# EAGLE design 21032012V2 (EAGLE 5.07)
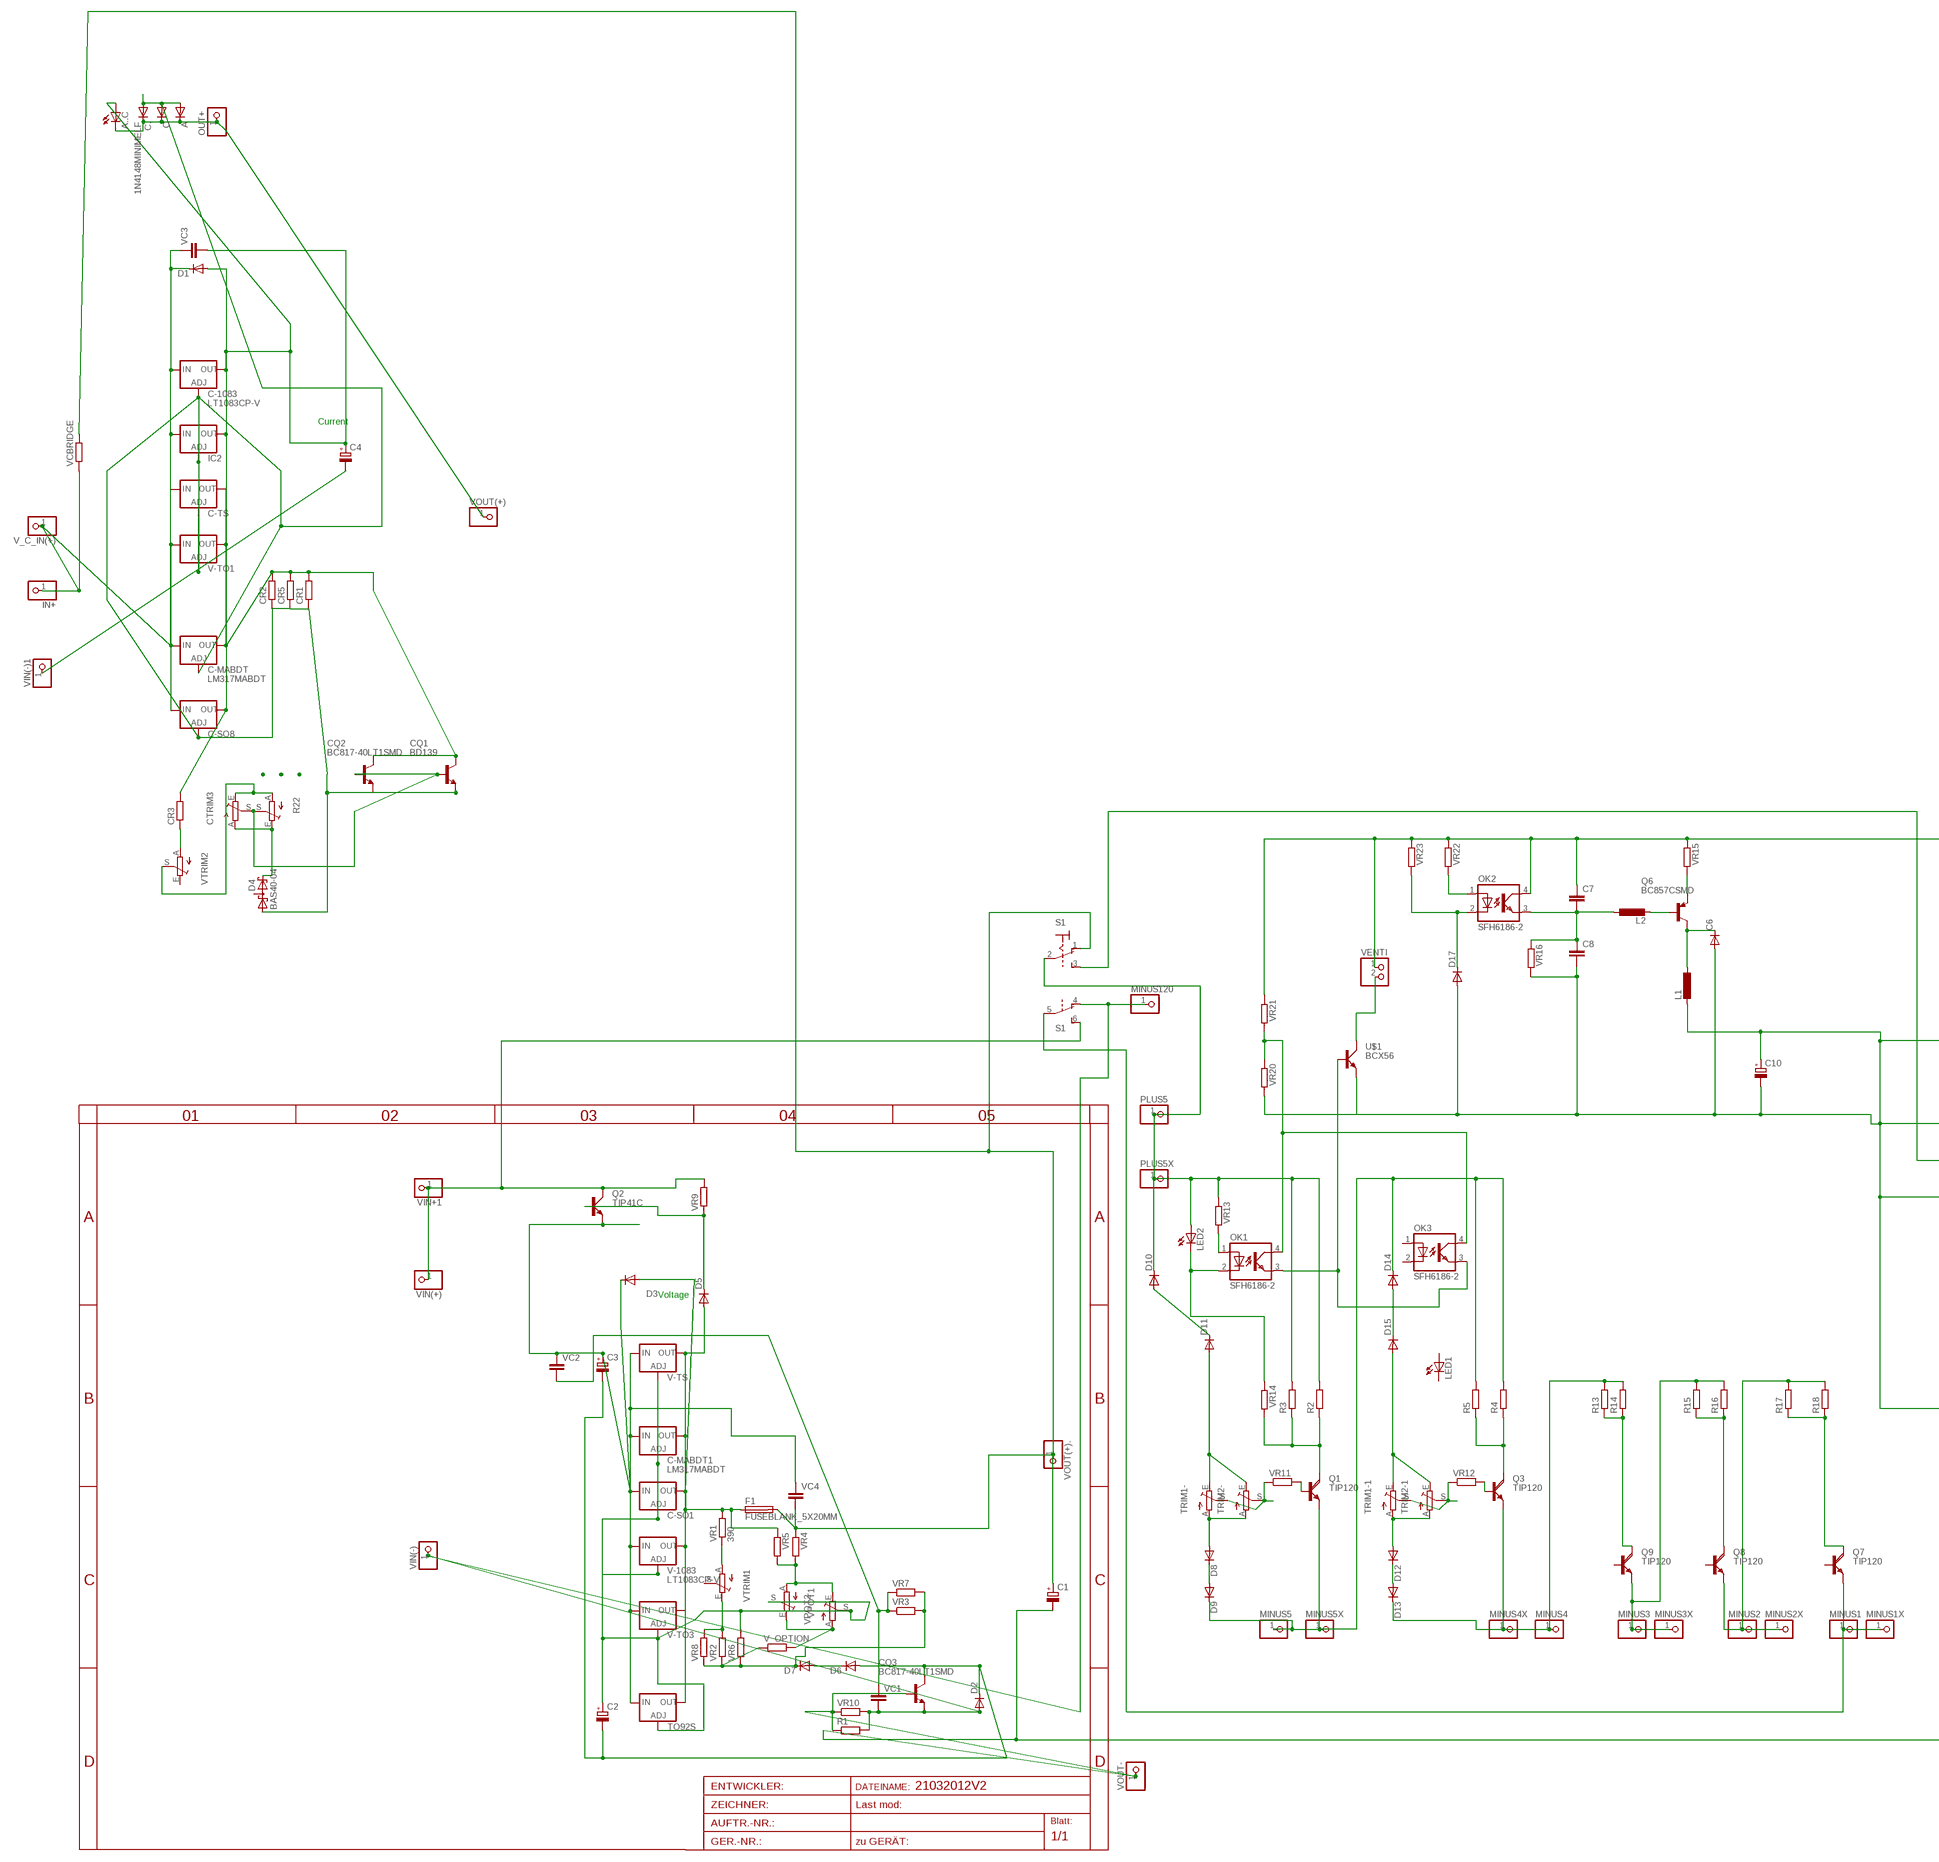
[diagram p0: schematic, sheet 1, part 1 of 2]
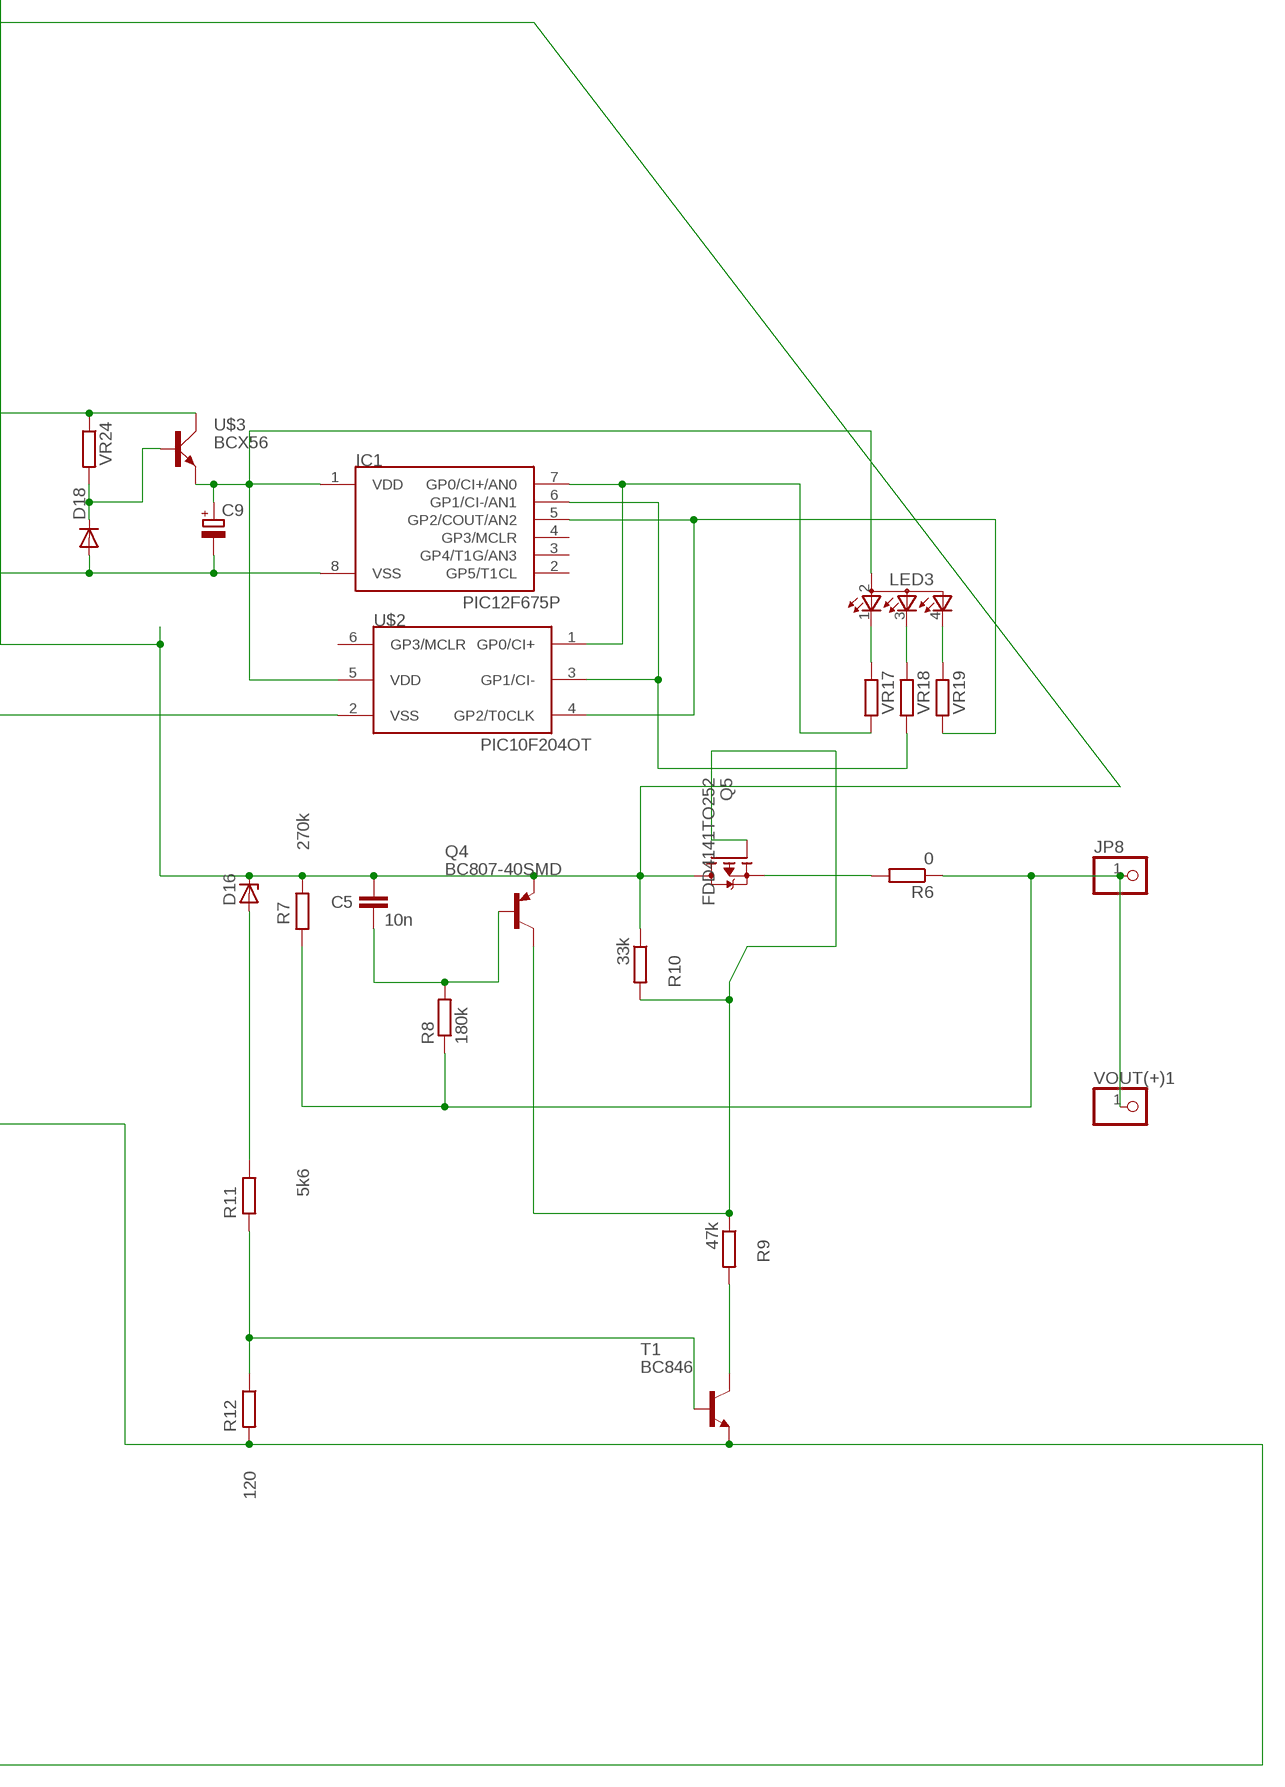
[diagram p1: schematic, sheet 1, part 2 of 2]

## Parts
A  DIODE-TO220V  [TO220ACS]
A..C  LED3MM  [LED3MM]
C  DIODE-SMB  [SMB]
C1  CPOL-EUE5-8.5  [E5-8,5]
C2  CPOL-EUE2.5-6  [E2,5-6]
C3  CPOL-EUE2.5-6  [E2,5-6]
C4  CPOL-EUE5-6  [E5-6]
C5  10n  C-EUC1206  [C1206]
C6  DIODE-SMB  [SMB]
C7  C-EUC0805  [C0805]
C8  C-EUC0805  [C0805]
C9  CPOL-EUE2.5-6  [E2,5-6]
C10  CPOL-EUE2.5-6  [E2,5-6]
C-1083  LT1083CP-V  [TO247S]
C-MABDT  LM317MABDT  [DPACK]
C-MABDT1  LM317MABDT  [DPACK]
C-SO1  LM317LM-OUTPIN7  [SO08]
C-SO8  LM317LM-OUTPIN7  [SO08]
C-TS  LM317TS  [317TS]
C.  1N4148MINIMELF  [MINIMELF]
CQ1  BD139  [TO126]
CQ2  BC817-40LT1SMD  [SOT23-BEC]
CQ3  BC817-40LT1SMD  [SOT23-BEC]
CR1  R-EU_R5025  [R5025]
CR2  R-EU_R1206  [R1206]
CR3  R-EU_0204/5  [0204/5]
CR5  R-EU_R1210  [R1210]
CTRIM3  TRIM_EU-EVND_H  [EVND8AA]
D1  DIODE-MINIMELF  [MINIMELF]
D2  DIODE-MINIMELF  [MINIMELF]
D3  DIODE-MINIMELF  [MINIMELF]
D4  BAS40-04  [SOT23]
D5  DIODE-MINIMELF  [MINIMELF]
D6  DIODE-MINIMELF  [MINIMELF]
D7  DIODE-MINIMELF  [MINIMELF]
D8  DIODE-MINIMELF  [MINIMELF]
D9  DIODE-MINIMELF  [MINIMELF]
D10  DIODE-MINIMELF  [MINIMELF]
D11  DIODE-MINIMELF  [MINIMELF]
D12  DIODE-MINIMELF  [MINIMELF]
D13  DIODE-MINIMELF  [MINIMELF]
D14  DIODE-MINIMELF  [MINIMELF]
D15  DIODE-MINIMELF  [MINIMELF]
D16  ZENER-DIODESOD80C  [SOD80C]
D17  DIODE-MINIMELF  [MINIMELF]
D18  DIODE-MINIMELF  [MINIMELF]
F1  FUSEBLANK_5X20MM  [FUSE_HOLDER_5X20MM]
IC1  PIC12F675P  [DIL8]
IC2  LM317LZS  [TO92S]
IN+  PINHD-1X1  [1X01]
JP8  PINHD-1X14.5MM  [1X4MM5]
L1  L-EUL5650M  [L5650M]
L2  L-EUL5650M  [L5650M]
LED1  LEDCHIPLED_1206  [CHIPLED_1206]
LED2  LEDCHIPLED_1206  [CHIPLED_1206]
LED3  TOPLED-3  [P-LCC-4-3]
MINUS1  PINHD-1X14.5MM  [1X4MM5]
MINUS1X  PINHD-1X11X0.4  [1X01]
MINUS2  PINHD-1X14.5MM  [1X4MM5]
MINUS2X  PINHD-1X11X0.4  [1X01]
MINUS3  PINHD-1X14.5MM  [1X4MM5]
MINUS3X  PINHD-1X11X0.4  [1X01]
MINUS4  PINHD-1X14.5MM  [1X4MM5]
MINUS4X  PINHD-1X11X0.4  [1X01]
MINUS5  PINHD-1X14.5MM  [1X4MM5]
MINUS5X  PINHD-1X11X0.4  [1X01]
MINUS120  PINHD-1X14.5MM  [1X4MM5]
OK1  SFH6186-2  [SMD4]
OK2  SFH6186-2  [SMD4]
OK3  SFH6186-2  [SMD4]
OUT+  PINHD-1X1  [1X01]
PLUS5  PINHD-1X14.5MM  [1X4MM5]
PLUS5X  PINHD-1X11X0.4  [1X01]
Q1  TIP120  [D-PAK_TO252AA]
Q2  TIP41C  [TO220AV]
Q3  TIP120  [D-PAK_TO252AA]
Q4  BC807-40SMD  [SOT23-BEC]
Q5  FDD4141TO252  [TO252]
Q6  BC857CSMD  [SOT23-BEC]
Q7  TIP120  [D-PAK_TO252AA]
Q8  TIP120  [D-PAK_TO252AA]
Q9  TIP120  [D-PAK_TO252AA]
R1  R-EU_0204/2V  [0204V]
R2  R-EU_CERAM55  [CERAM55]
R3  R-EU_CERAM55  [CERAM55]
R4  R-EU_CERAM55  [CERAM55]
R5  R-EU_CERAM55  [CERAM55]
R6  0  R-EU_R2010  [R2010]
R7  270k  R-EU_R1206  [R1206]
R8  180k  R-EU_R1206  [R1206]
R9  47k  R-EU_R1206  [R1206]
R10  33k  R-EU_R1206  [R1206]
R11  5k6  R-EU_R1206  [R1206]
R12  120  R-EU_R1206  [R1206]
R13  R-EU_CERAM55  [CERAM55]
R14  R-EU_CERAM55  [CERAM55]
R15  R-EU_CERAM55  [CERAM55]
R16  R-EU_CERAM55  [CERAM55]
R17  R-EU_CERAM55  [CERAM55]
R18  R-EU_CERAM55  [CERAM55]
R22  TRIM_EU-RAND160  [RANDL]
S1  320-938  [320-938]
T1  BC846  [SOT23]
TO92S  LM317LZS  [TO92S]
TRIM1-  TRIM_EU-EVND_H  [EVND8AA]
TRIM1-1  TRIM_EU-EVND_H  [EVND8AA]
TRIM2-  TRIM_EU-S64W  [S64W]
TRIM2-1  TRIM_EU-S64W  [S64W]
U$1  BCX56  [SOT223]
U$2  PIC10F204OT  [SOT23-6]
U$3  BCX56  [SOT223]
V-1083  LT1083CP-V  [TO247S]
V-TO1  LM317-TO3  [TO3-K02]
V-TO3  LM317-TO3  [TO3-K02]
V-TS  LM317TS  [317TS]
V_C_IN(+)  PINHD-1X11X0.4  [1X01]
V_OPTION  R-EU_0204/2V  [0204V]
VC1  C-EU050-025X075  [C050-025X075]
VC2  C-EU050-025X075  [C050-025X075]
VC3  C-EU050-025X075  [C050-025X075]
VC4  C-EUC1206  [C1206]
VCBRIDGE  R-EU_R0402  [R0402]
VENTI  PINHD-1X2  [1X02]
VIN(+)  PINHD-1X11X0.4  [1X01]
VIN(-)  PINHD-1X1  [1X01]
VIN(-)1  PINHD-1X1  [1X01]
VIN+1  PINHD-1X1  [1X01]
VOUT(+)  PINHD-1X11X0.4  [1X01]
VOUT(+)1  PINHD-1X11X0.4  [1X01]
VOUT(+).  PINHD-1X11X0.4  [1X01]
VOUT-  PINHD-1X11X0.4  [1X01]
VPOT1  TRIM_EU-RAND160  [RANDL]
VPOT2  TRIM_EU-S64W  [S64W]
VR1  390  R-EU_0207/15  [0207/15]
VR2  R-EU_0204/2V  [0204V]
VR3  R-EU_0204/5  [0204/5]
VR4  R-EU_R1206  [R1206]
VR5  R-EU_R1206  [R1206]
VR6  R-EU_R1206  [R1206]
VR7  R-EU_R1206  [R1206]
VR8  R-EU_R1206  [R1206]
VR9  R-EU_R1206  [R1206]
VR10  R-EU_0617/17  [0617/17]
VR11  R-EU_R1206  [R1206]
VR12  R-EU_R1206  [R1206]
VR13  R-EU_R1206  [R1206]
VR14  R-EU_R1206  [R1206]
VR15  R-EU_R1206  [R1206]
VR16  R-EU_R1206  [R1206]
VR17  R-EU_R1206  [R1206]
VR18  R-EU_R1206  [R1206]
VR19  R-EU_R1206  [R1206]
VR20  R-EU_R1206  [R1206]
VR21  R-EU_R1206  [R1206]
VR22  R-EU_R1206  [R1206]
VR23  R-EU_R1206  [R1206]
VR24  R-EU_R1206  [R1206]
VTRIM1  TRIM_EU-EVND_H  [EVND8AA]
VTRIM2  TRIM_EU-EVND_H  [EVND8AA]

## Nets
ADJ2: C2.+ C-MABDT1.1(ADJ) C-SO1.4(ADJ) TO92S.1(ADJ) V-1083.1(ADJ) V-TO3.2(ADJ) V-TS.1(ADJ) VPOT1.S VPOT2.S VR6.2
ADJUST: A.A C-1083.1(ADJ) C-MABDT.1(ADJ) C-SO8.4(ADJ) C-TS.1(ADJ) C..A C.A CQ1.1(E) CQ2.E CR1.1 CR2.1 CR5.1 D4.1(A1) IC2.1(ADJ) V-TO1.2(ADJ)
B: TRIM1-.S TRIM2-.S VR11.1
B1: CQ1.3(B) CQ2.B CTRIM3.S R22.S
B2: TRIM1-1.S TRIM2-1.S VR12.1
B-Q1: C5.2 Q4.B R8.2
BATT-: MINUS1.1 MINUS1X.1 Q7.3(E) S1.5(B:P)
D: Q5.3(S) R6.2
GATE: Q4.C Q5.1(G) R9.1 R10.2
IN+1: C3.+ C-MABDT1.3(IN) C-SO1.1(IN) D3.C Q2.E TO92S.3(IN) V-1083.3(IN) V-TO3.1(IN) V-TS.3(IN) VC2.1 VC4.1
IN-: CQ3.E D2.A MINUS120.1 R1.2 S1.4(B:O) VC1.2 VIN(-).1 VR10.2
INPUT+: C-1083.3(IN) C-MABDT.3(IN) C-SO8.1(IN) C-TS.3(IN) D1.C IC2.3(IN) IN+.1 V-TO1.1(IN) V_C_IN(+).1 VC3.1 VCBRIDGE.1
MINUS: CTRIM3.A D4.2(C2) R22.E
N$1: V_OPTION.2 VPOT1.E VPOT2.A
N$2: VPOT1.A VPOT2.E VR4.2 VR5.2
N$3: VR2.2 VR8.2 VTRIM1.E
N$4: VR1.1 VTRIM1.A
N$5: CTRIM3.E R22.A VTRIM2.S
N$6: CR3.1 VTRIM2.A
N$7: VC1.1 VC2.2 VR3.1 VR7.1
N$8: D13.C MINUS4.1 MINUS4X.1 Q3.3(E) R13.2 R14.2
N$9: C4.- VIN(-)1.1
N$10: D5.C Q2.B VR9.1
N$11: LED2.C OK1.2(C) VR14.1
N$12: D7.C V_OPTION.1 VR2.1 VR3.2 VR6.1 VR7.2 VR8.1
N$13: D6.C D7.A
N$14: D11.A TRIM1-.E TRIM2-.E
N$15: D8.A TRIM1-.A TRIM2-.A
N$16: D10.C LED2.A PLUS5.1 PLUS5X.1 R2.2 R3.2 S1.2(1:P) VR13.1
N$17: D10.A D11.C
N$18: R9.2 T1.3(C)
N$19: D16.A R11.1
N$20: Q1.4(C) R2.1 R3.1 VR14.2
N$21: R11.2 R12.1 T1.1(B)
N$23: OK1.1(A) VR13.2
N$24: D8.C D9.A
N$25: Q1.1(B) VR11.2
N$26: D15.A TRIM1-1.E TRIM2-1.E
N$27: D12.A TRIM1-1.A TRIM2-1.A
N$28: D9.C D14.C MINUS5.1 MINUS5X.1 Q1.3(E) R4.2 R5.2
N$29: D14.A D15.C
N$30: Q3.4(C) R4.1 R5.1
N$32: D12.C D13.A
N$33: Q3.1(B) VR12.2
N$34: C9.+ IC1.1(VDD) LED3.2(A2) U$2.5(VDD) U$3.1(E)
N$35: IC1.7(GP0/CI+/AN0) U$2.1(GP0/CI+) VR17.2
N$36: IC1.6(GP1/CI-/AN1) U$2.3(GP1/CI-) VR18.2
N$37: IC1.5(GP2/COUT/AN2) U$2.4(GP2/T0CLK) VR19.2
N$38: Q6.E VR15.2
N$39: L2.2 Q6.B
N$40: C6.C L1.1 Q6.C
N$41: D17.C OK2.2(C) VR23.2
N$42: OK2.1(A) VR22.2
N$43: C7.2 C8.1 L2.1 OK2.3(EMIT) VR16.1
N$44: OK1.4(COL) OK3.4(COL) VR20.1 VR21.2
N$45: OK1.3(EMIT) OK3.3(EMIT) U$1.3(B)
N$46: D18.C U$3.3(B) VR24.2
N$47: LED3.1(CRED) VR17.1
N$48: LED3.3(CBLUE) VR18.1
N$49: LED3.4(CGREEN) VR19.1
N$53: U$1.2(C) VENTI.2
N$56: Q9.4(C) R13.1 R14.1
N$58: Q8.4(C) R15.1 R16.1
N$59: MINUS3.1 MINUS3X.1 Q9.3(E) R15.2 R16.2
N$60: MINUS2.1 MINUS2X.1 Q8.3(E) R17.2 R18.2
N$61: Q7.4(C) R17.1 R18.1
OUT1: A..C.A C4.+ C-1083.2(OUT) C-MABDT.4(OUT) C-SO8.7(OUT) C-TS.2(OUT) CQ1.2(C) CQ2.C CR1.2 CR2.2 CR3.2 CR5.2 D1.A IC2.2(OUT) V-TO1.3(OUT) VC3.2
OUT2: C-MABDT1.4(OUT) C-SO1.7(OUT) D3.A D5.A F1.1 TO92S.2(OUT) V-1083.2(OUT) V-TO3.3(OUT) V-TS.2(OUT) VR1.2 VR5.1
OUT+: A..C.K(C) A.C C..C C.C OUT+.1 VOUT(+).1
V+OUT: JP8.1 R6.1 R7.2 R8.1 VOUT(+)1.1
V-: C1.- C6.A C8.2 C9.- C10.+ C10.- CQ3.B D17.A D18.A IC1.8(VSS) L1.2 R1.1 R12.2 T1.2(E) U$1.1(E) U$2.2(VSS) U$3.2(C) VOUT-.1 VR10.1 VR16.2 VR20.2 VR24.1
VIN+: Q2.C S1.6(B:S) VIN(+).1 VIN+1.1 VR9.2
VIRT-: C2.- C3.- CQ3.C D2.C D6.A
VOUT+: C1.+ F1.2 S1.1(1:O) VC4.2 VCBRIDGE.2 VOUT(+)..1 VR4.1
VOUT+120: C5.1 C7.1 D16.C OK2.4(COL) Q4.E Q5.2(D) R7.1 R10.1 S1.3(1:S) VENTI.1 VR15.1 VR21.1 VR22.1 VR23.1
Unconnected: D4.3(C1A2) IC1.2(GP5/T1CL) IC1.3(GP4/T1G/AN3) IC1.4(GP3/MCLR) LED1.A LED1.C OK3.1(A) OK3.2(C) Q7.1(B) Q8.1(B) Q9.1(B) U$2.6(GP3/MCLR) VTRIM1.S VTRIM2.E

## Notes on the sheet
- Current
- Voltage

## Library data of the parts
A C C6 D1-D3 D5-D15 D17 D18 = diode:DIODE-: DIODE
A..C LED1 LED2 = led:LED: LED
C1-C4 C9 C10 = rcl:CPOL-EU: POLARIZED CAPACITOR, European symbol
C5 = rcl-2:C-EU: CAPACITOR, European symbol
C7 C8 VC1-VC4 = rcl:C-EU: CAPACITOR, European symbol
C-1083 V-1083 = linear-technology-2:LT1083*: 7.5A Low Dropout Positive Adjustable Regulators
C-MABDT C-MABDT1 = v-reg:LM317?*: 500 mA Adjustable Output Positive Voltage Regulator Source: http://www.onsemi.co.jp .. LM317M-D.PDF
C-SO1 C-SO8 IC2 TO92S = v-reg-3:LM317L: Adjustable Voltage Regulator, 1.2V to 37V, 100mA
C-TS V-TS = v-reg:LM317TS: VOLTAGE REGULATOR
C. = diode-1:1N4148: DIODE
CQ1 = transistor-npn:BD139*: NPN Transistor
CQ2 CQ3 = transistor-npn:BC817*: NPN Transistor
CR1-CR3 CR5 R6-R12 V_OPTION VCBRIDGE VR1-VR24 = rcl-2:R-EU_: RESISTOR, European symbol
CTRIM3 R22 TRIM1- TRIM1-1 TRIM2- TRIM2-1 VPOT1 VPOT2 VTRIM1 VTRIM2 = pot:TRIM_EU-: POTENTIOMETER
D4 = diode:BAS40-04: Silicon Schottky Diodes General-purpose diode for high-speed switching
D16 = diode-1:ZENER-DIODE: Z-Diode
F1 = fuse:FUSE: Fuse
IC1 = microchip-5:PIC12F6*: uPC nW 1k Program Flash memory 2x Timer Comparator 10b A/D converter/ 4xIN
IN+ OUT+ VIN(-) VIN(-)1 VIN+1 = pinhead(2):PINHD-1X1: PIN HEADER
JP8 MINUS1 MINUS1X MINUS2 MINUS2X MINUS3 MINUS3X MINUS4 MINUS4X MINUS5 MINUS5X MINUS120 PLUS5 PLUS5X V_C_IN(+) VIN(+) VOUT(+) VOUT(+)1 VOUT(+). VOUT- = pinhead:PINHD-1X1: PIN HEADER
L1 L2 = rcl:L-EU: INDUCTOR, European symbol
LED3 = led:TOPLED-3: OSRAM - Hyper Multi TOPLED® (RGB) LB E673, LV E673, LT E673 - Power TOPLED® Enhanced optical Power LED (HOP2000) LS E67B, LA E67B, LO E67B, LY E67B - Hyper Multi TOPLED® Enhanced optical Power LED (HOP2000 / ATON®) LATB T66B - Hyper Multi TOPLED® Hyper-Bright LED LATB T686 Source: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
OK1-OK3 = optocoupler:SFH618?*: Optocoupler, Phototransistor Output, Low Input Current Source: http://www.vishay.com/docs/83673/sfh618.pdf
Q1 Q3 Q7-Q9 = transistor-power:TIP120: NPN DARLINGTON TRANSISTOR
Q2 = transistor-power:TIP41C: NPN TRANSISTOR
Q4 = transistor-pnp:BC807*: PNP Transistror
Q5 = transistor-fet:FDD4141: P-Channel PowerTrench® MOSFET Source: FDD4141.pdf
Q6 = transistor-pnp:BC857*: PNP Transistror
R1-R5 R13-R18 = rcl:R-EU_: RESISTOR, European symbol
S1 = switch:320-938: TOGGLE SWITCH distributor RS Components
T1 = transistor:BC846: NPN TRANSISTOR
U$1 U$3 = transistor-power:BCX56
U$2 = microchip-5:PIC10F2*: uPC nW 0,25/0,5k Program Flash memory Comparator
V-TO1 V-TO3 = v-reg:LM317-TO3: VOLTAGE REGULATOR
VENTI = pinhead(2):PINHD-1X2: PIN HEADER

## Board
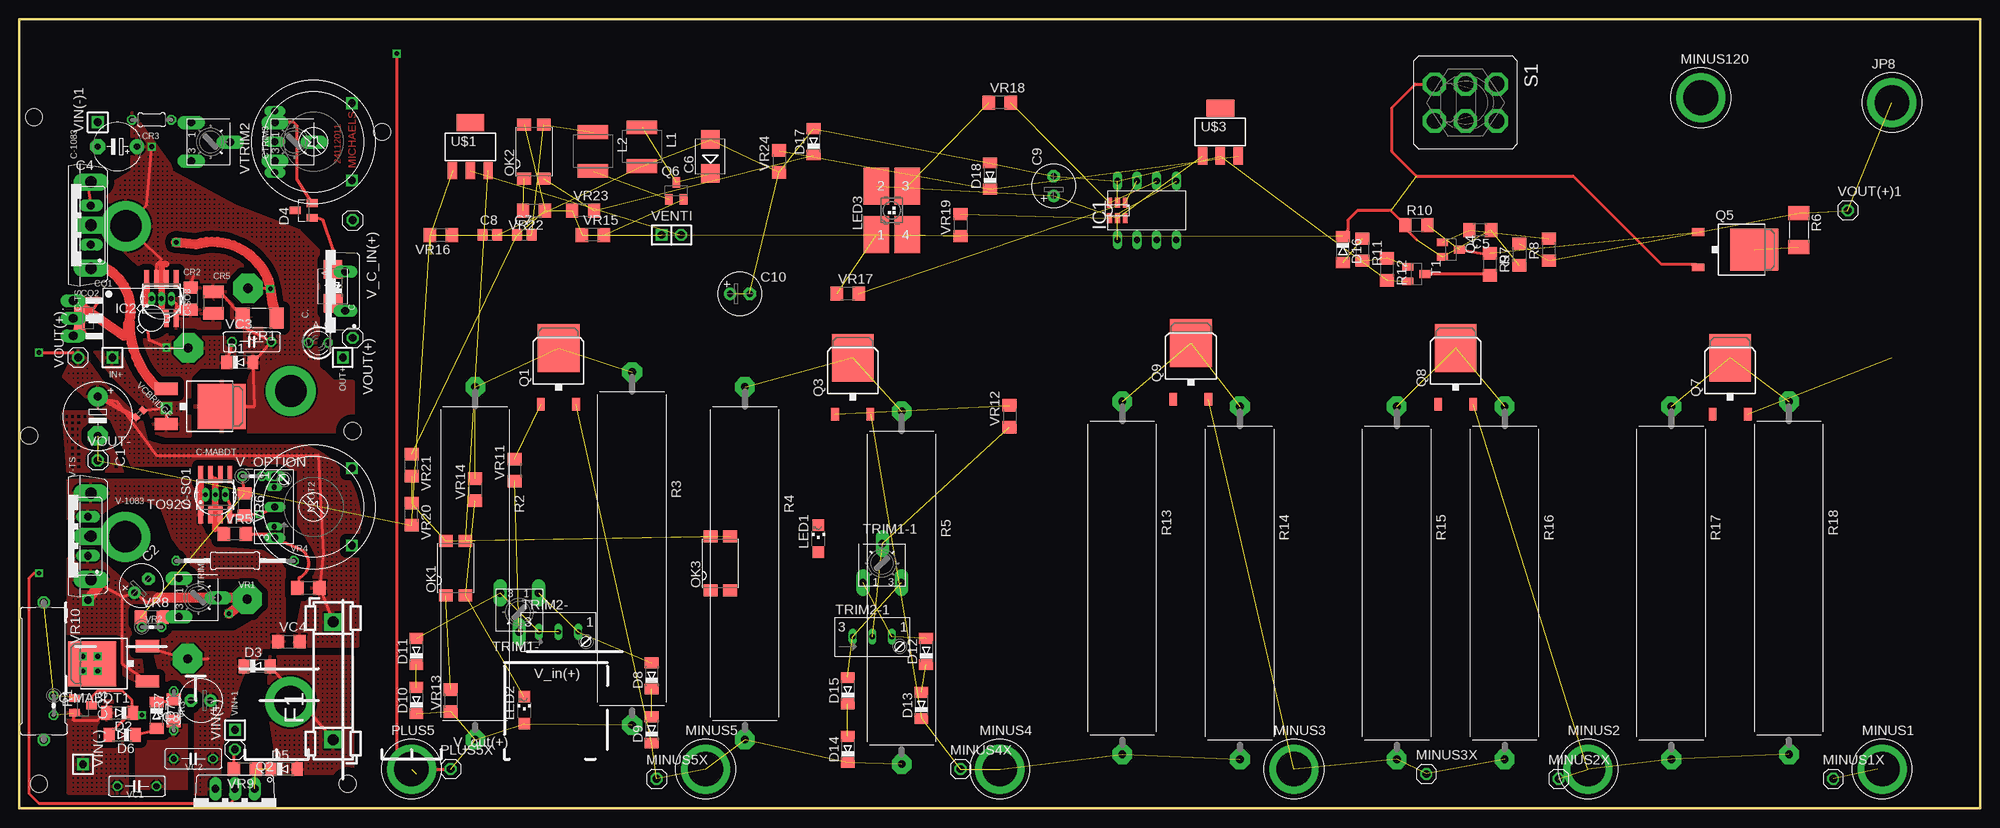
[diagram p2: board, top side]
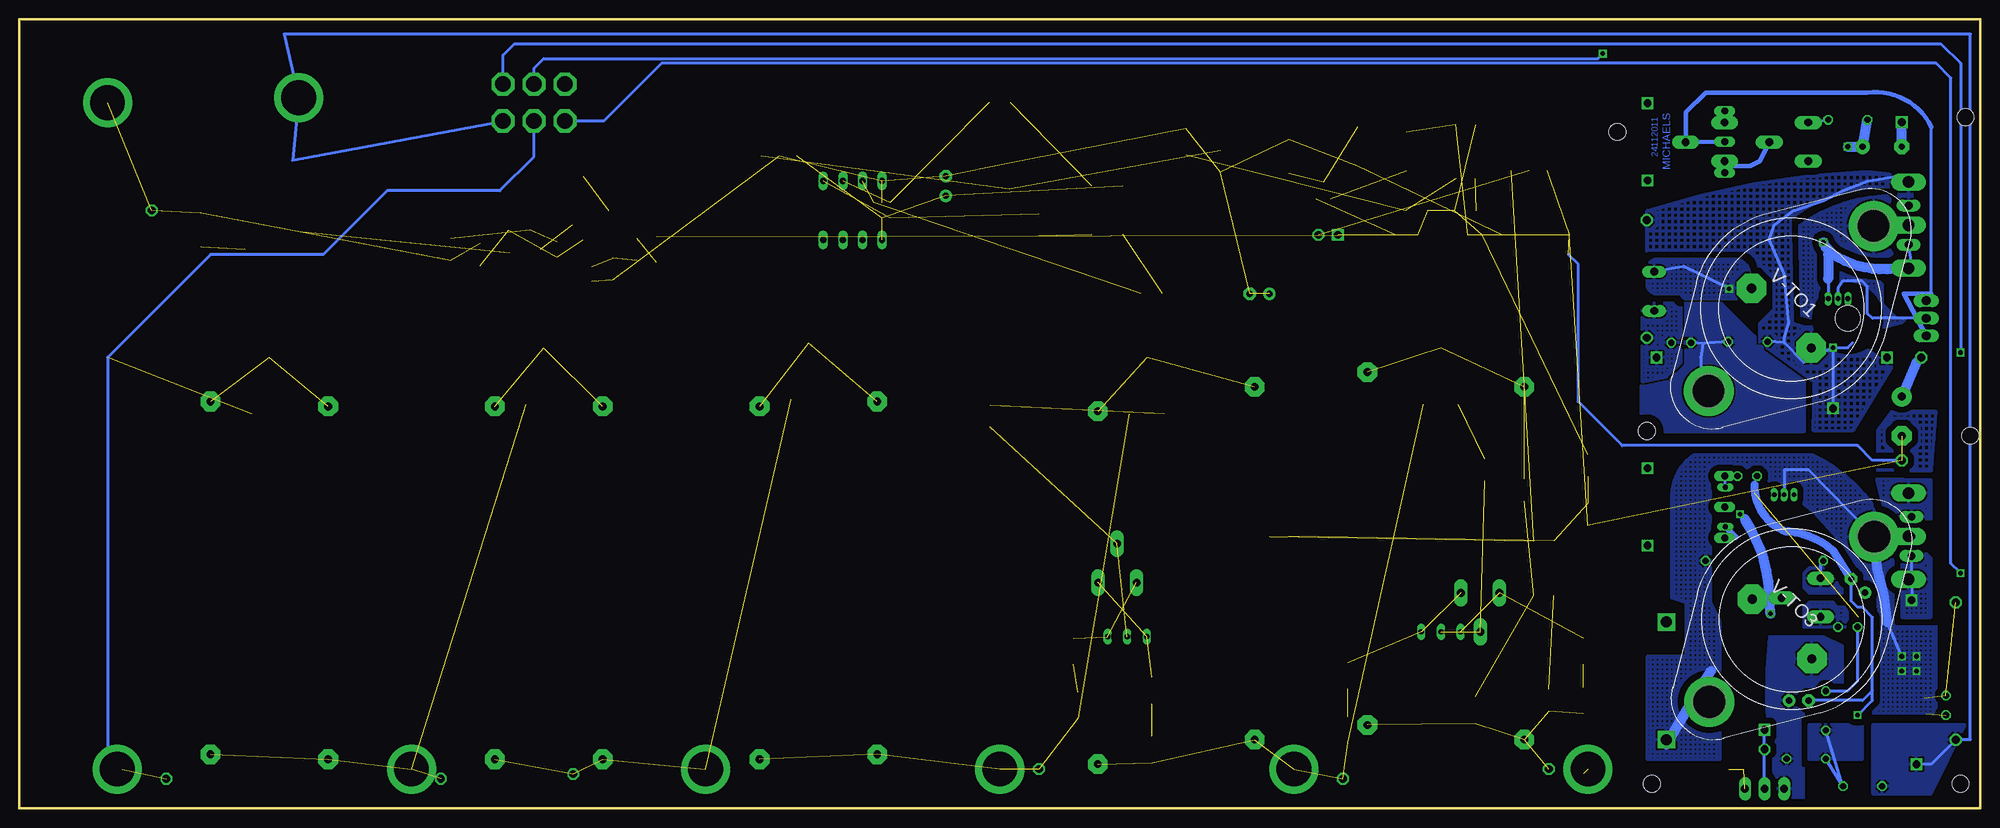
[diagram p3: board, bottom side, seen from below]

Size 254 x 102.23 mm. Coordinates in mm from the lower left corner, seen from the top.
Outline: 254,0 254,102.23 0,102.23 0,0 254,0
Copper layers (1*16): Top 0.035mm / dielectric 1.5mm / Bottom 0.035mm
Design rules "default *": minimum track width 10mil, minimum drill 24mil, track to track 8mil, track to pad 8mil, pad to pad 8mil, via to via 8mil, smd to smd 8mil, copper to edge 40mil, drill to drill 8mil, minimum pad ring 1mil, minimum via ring 8mil, stop-mask expansion 4mil, vias tented up to drill 0mil, thermal gap 10mil
Holes 2.2 mm at 46.99,87.63 1.27,48.26 43.18,48.9 1.91,89.53 42.55,3.17 2.54,3.17

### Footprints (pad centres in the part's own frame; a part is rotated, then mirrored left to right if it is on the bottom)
TO220ACS = drill 1.016 long: A 2.54,-2.54; C -2.54,-2.54
LED3MM = drill 0.813 octagon: A -1.27,0; K 1.27,0
SMB = smd 2.4 x 2.4: A 2.2,0; C -2.2,0
E5-8,5 = drill 1.016 pad 2.54 round: + -2.54,0 | drill 1.016 pad 2.54 octagon: - 2.54,0
E2,5-6 = drill 0.813 pad 1.6 round: + -1.27,0 | drill 0.813 pad 1.6 octagon: - 1.27,0
E5-6 = drill 0.813 pad 1.905 round: + -2.54,0 | drill 0.813 pad 1.905 octagon: - 2.54,0
C1206 = smd 1.6 x 1.8: 1 -1.4,0; 2 1.4,0
C0805 = smd 1.3 x 1.5: 1 -0.95,0; 2 0.95,0
TO247S = drill 1.499 long: 1 -5.588,-2.921; 2 0,-2.921; 3 5.588,-2.921
DPACK = smd 1.6 x 3: 1 -2.28,-4.8; 3 2.28,-4.8 | smd 5.8 x 6.2: 4 0,2.38
SO08 = smd 0.6 x 2.2: 1 -1.905,-2.6; 2 -0.635,-2.6; 3 0.635,-2.6; 4 1.905,-2.6; 5 1.905,2.6; 6 0.635,2.6; 7 -0.635,2.6; 8 -1.905,2.6
317TS = drill 1.016 long: 1 -2.54,-2.54; 2 0,-2.54; 3 2.54,-2.54
MINIMELF = smd 1.4 x 1.8: A 1.7,0; C -1.7,0
TO126 = drill 1.118 long: 1 -2.286,-5.08; 2 0,-5.08; 3 2.286,-5.08 | hole 3.302: 0,5.08
SOT23-BEC = smd 1 x 1.4: B -0.95,-1.1; C 0,1.1; E 0.95,-1.1
R5025 = smd 1.8 x 2.7: 1 -2.2,0; 2 2.2,0
R1206 = smd 1.6 x 1.803: 1 -1.422,0; 2 1.422,0
0204/5 = drill 0.813 octagon: 1 -2.54,0; 2 2.54,0
R1210 = smd 1.6 x 2.7: 1 -1.4,0; 2 1.4,0
EVND8AA = drill 1 pad 1.778 long: A -2.5,-2.5; E 2.5,-2.5; S 0.04,2.54
SOT23 = smd 1 x 1.4: 1 -0.95,-1.1; 2 0.95,-1.1; 3 0,1.1
SOD80C = smd 1.4 x 1.8: A 1.7,0; C -1.7,0
FUSE_HOLDER_5X20MM = drill 1.422 pad 2.286 square: 1 0,0; 2 15.24,0
DIL8 = drill 0.813 long: 1 -3.81,-3.81; 2 -1.27,-3.81; 3 1.27,-3.81; 4 3.81,-3.81; 5 3.81,3.81; 6 1.27,3.81; 7 -1.27,3.81; 8 -3.81,3.81
TO92S = drill 0.6 pad 0.813 long: 1 -1.27,0; 2 0,0; 3 1.27,0
1X01 = drill 1.016 square: 1 0,0
1X4MM5 = drill 4.5 pad 6.35 round: 1 0,0
L5650M = smd 1.8 x 4: 1 -2.5,0; 2 2.5,0
CHIPLED_1206 = smd 1.5 x 1.5: A 0,-1.75; C 0,1.75
P-LCC-4-3 = smd 3.3 x 4.8: 1 -2,-3.15; 2 -2,3.15; 3 2,3.15; 4 2,-3.15
1X01' = drill 1.016 octagon: 1 0,0
SMD4 = smd 1.78 x 1.55: 1 -1.27,-3.5; 2 1.27,-3.5; 3 1.27,3.5; 4 -1.27,3.5
D-PAK_TO252AA = smd 1 x 1.6: 1 -2.28,-4.8; 3 2.28,-4.8 | smd 5.4 x 6.2: 4 0,2.5
TO220AV = drill 1.016 long: B -2.54,-2.54; C 0,-2.54; E 2.54,-2.54
TO252 = smd 1 x 1.6: 1 -2.28,-4.8; 2 2.28,-4.8 | smd 5.4 x 6.2: 3 0,2.5
0204V = drill 0.813 octagon: 1 -1.27,0; 2 1.27,0
CERAM55 = drill 1 pad 2.54 octagon: 1 -22.86,0; 2 22.86,0
R2010 = smd 1.8 x 2.7: 1 -2.2,0; 2 2.2,0
RANDL = drill 0.9 long: A -4,5; E 4,5; S 0,5 | drill 1 square: P$1 -5,-5; P$2 5,-5
320-938 = drill 2.007 octagon: 1 -2.388,4.013; 2 -2.388,0; 3 -2.388,-4.013; 4 2.388,4.013; 5 2.388,0; 6 2.388,-4.013
S64W = drill 0.7 long: A 2.54,1.27; E -2.54,1.27; S 0,1.27
SOT223 = smd 1.219 x 2.235: 1 -2.311,-3.099; 2 0,-3.099; 3 2.311,-3.099 | smd 3.6 x 2.2: 4 0,3.099
SOT23-6 = smd 0.635 x 1.27: 1 -1.016,-1.016; 2 0,-1.016; 3 1.016,-1.016; 4 1.016,1.016; 5 0,1.016; 6 -1.016,1.016
TO3-K02 = drill 1.194 pad 3.81 octagon: 1 -1.778,-5.461; 2 -1.778,5.461 | drill 4.115 pad 6.477 round: 3 15.113,0; 3@ -15.113,0
C050-025X075 = drill 0.813 octagon: 1 -2.54,0; 2 2.54,0
R0402 = smd 0.7 x 0.9: 1 -0.65,0; 2 0.65,0
1X02 = drill 1.016 square: 1 -1.27,0 | drill 1.016 octagon: 2 1.27,0
0207/15 = drill 0.813 octagon: 1 -7.62,0; 2 7.62,0
0617/17 = drill 1.016 octagon: 1 -8.89,0; 2 8.89,0

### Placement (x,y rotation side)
A  39.69,66.99 90 top
A..C  38.73,60.33 0 top
C  40.64,67.63 90 top
C1  10.16,50.8 270 top
C2  15.81,28.83 45 top
C3  23.5,13.97 180 top
C4  12.7,85.72 180 top
C5  189.23,74.93 180 top
C6  89.53,84.45 90 top
C7  65.41,74.3 0 top
C8  60.96,74.3 0 top
C9  133.99,80.64 90 top
C10  93.34,66.67 0 top
C-1083  6.35,75.56 90 top
C-MABDT  23.81,52.07 270 top
C-MABDT1  11.81,18.73 90 top
C-SO1  25.4,40.64 0 top
C-SO8  18.41,66.04 0 top
C-TS  6.73,75.56 90 top
C.  40.96,67.63 90 top
CQ1  12.06,63.5 270 top
CQ2  8.89,63.5 270 top
CQ3  8.26,13.34 270 top
CR1  31.11,63.5 180 top
CR2  22.23,66.04 90 top
CR3  17.14,89.22 180 top
CR5  25.15,65.53 90 top
CTRIM3  35.61,86.36 270 top
D1  28.57,57.78 0 top
D2  13.02,12.38 180 top
D3  30.8,18.41 0 top
D4  36.83,77.47 90 top
D5  34.29,5.08 0 top
D6  13.34,9.53 180 top
D7  17.78,12.06 270 top
D8  81.92,17.14 90 top
D9  81.92,10.16 90 top
D10  51.44,13.97 90 top
D11  51.44,20.32 90 top
D12  117.47,20.32 90 top
D13  116.84,13.34 90 top
D14  107.31,7.62 90 top
D15  107.31,15.24 90 top
D16  171.45,72.39 270 top
D17  102.87,86.36 90 top
D18  125.73,81.92 90 top
F1  40.64,8.89 90 top
IC1  146.05,77.47 0 top
IC2  18.41,66.04 180 top
IN+  12.06,58.42 90 top
JP8  242.57,91.44 0 top
L1  80.64,85.72 270 top
L2  74.3,85.09 270 top
LED1  103.5,34.92 0 top
LED2  65.41,12.7 0 top
LED3  113.03,77.47 0 top
MINUS1  241.3,5.08 0 top
MINUS1X  [1X01']  234.95,3.81 0 top
MINUS2  203.2,5.08 0 top
MINUS2X  [1X01']  199.39,3.81 0 top
MINUS3  165.1,5.08 0 top
MINUS3X  [1X01']  182.25,4.45 0 top
MINUS4  127,5.08 0 top
MINUS4X  [1X01']  121.92,5.08 0 top
MINUS5  88.9,5.08 0 top
MINUS5X  [1X01']  82.55,3.81 0 top
MINUS120  217.81,92.08 0 top
OK1  56.52,31.11 0 top
OK2  66.67,85.09 0 top
OK3  90.81,31.75 0 top
OUT+  41.91,58.42 180 top
PLUS5  50.8,5.08 0 top
PLUS5X  [1X01']  55.88,5.08 0 top
Q1  69.85,57.15 0 top
Q2  27.94,0 180 top
Q3  107.95,55.88 0 top
Q4  185.42,72.39 270 top
Q5  222.25,72.39 270 top
Q6  85.09,80.01 0 top
Q7  221.62,55.88 0 top
Q8  186.06,57.15 0 top
Q9  151.76,57.78 0 top
R1  4.45,13.34 270 top
R2  59.05,31.75 270 top
R3  79.38,33.66 270 top
R4  93.98,31.75 270 top
R5  114.3,28.57 270 top
R6  230.5,74.93 270 top
R7  194.31,71.75 90 top
R8  198.12,72.39 90 top
R9  190.5,70.48 270 top
R10  180.97,75.56 0 top
R11  173.99,72.39 270 top
R12  177.16,69.85 270 top
R13  142.88,29.84 270 top
R14  158.12,29.21 270 top
R15  178.44,29.21 270 top
R16  192.41,29.21 270 top
R17  214,29.21 270 top
R18  229.24,29.84 270 top
R22  38.1,86.36 90 top
S1  187.32,91.44 270 top
T1  180.97,69.22 270 top
TO92S  25.4,40.64 180 top
TRIM1-  64.77,25.4 180 top
TRIM1-1  111.76,31.75 0 top
TRIM2-  69.85,21.59 0 top
TRIM2-1  110.49,20.95 0 top
U$1  58.42,85.72 0 top
U$2  142.24,77.47 180 top
U$3  155.57,87.63 0 top
V-1083  6.35,35.24 90 top
V-TO1  24.5,64.77 45 bottom
V-TO3  24.4,24.5 45 bottom
V-TS  6.35,35.24 90 top
V_C_IN(+)  [1X01']  43.18,76.2 90 top
V_OPTION  30.16,43.05 0 top
VC1  15.24,2.86 180 top
VC2  22.54,6.41 180 top
VC3  30.1,60.45 0 top
VC4  34.92,21.59 0 top
VCBRIDGE  15.56,51.12 225 top
VENTI  84.45,74.3 0 top
VIN(+)  [1X01']  27.94,7.62 90 top
VIN(-)  8.26,5.71 90 top
VIN(-)1  10.16,88.9 90 top
VIN+1  27.94,10.16 90 top
VOUT(+)  [1X01']  43.18,60.96 90 top
VOUT(+)1  [1X01']  236.85,77.47 0 top
VOUT(+).  [1X01']  7.62,58.42 90 top
VOUT-  [1X01']  10.16,45.09 0 top
VPOT1  38.1,39.05 90 top
VPOT2  34.29,39.05 90 top
VR1  27.94,32.07 0 top
VR2  17.14,23.5 0 top
VR3  20,12.64 90 top
VR4  37.47,28.57 180 top
VR5  27.94,35.56 0 top
VR6  29.21,39.37 270 top
VR7  20,12.7 90 top
VR8  17.14,24.77 0 top
VR9  29.21,5.08 180 top
VR10  3.17,17.78 270 top
VR11  64.14,43.81 90 top
VR12  128.27,50.8 90 top
VR13  55.88,13.97 90 top
VR14  59.05,41.27 90 top
VR15  74.3,74.3 0 top
VR16  54.61,74.3 180 top
VR17  107.31,66.67 0 top
VR18  127,91.44 0 top
VR19  121.92,75.56 90 top
VR20  50.8,38.1 270 top
VR21  50.8,44.45 270 top
VR22  66.67,77.47 180 top
VR23  73.03,77.47 0 top
VR24  98.42,83.82 90 top
VTRIM1  23.18,27.3 270 top
VTRIM2  24.77,86.36 270 top

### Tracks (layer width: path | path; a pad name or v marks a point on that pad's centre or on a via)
ADJ2  (via drill 0.6, 1)
  Top 0.406: TO92S.1 27.3,39.37 C-SO1.4 27.3,37.95 VR6.2 v31.11,38.1 VPOT2.S VPOT1.S | 17.98,27.3 16.51,26.67 C2.+ 13.36,27.36 | 13.36,27.36 V-1083.1 | C-MABDT1.1 13.34,18.73 13.36,27.36 | 29.84,27.3 V-TO3.2
  Top 1.27: v8.89,26.99 10.16,28.57 | 17.98,27.3 29.84,27.3 | V-TO3.2 v27.16,25.21
  Bottom 0.406: 9.62,29.3 V-1083.1 8.89,30.04 V-TS.1 | 9.62,29.3 10.16,28.77 | 9.62,29.3 8.89,28.57 v8.89,26.99 8.26,26.67 | 30.48,37.47 v31.11,38.1
  Bottom 1.27: 30.48,37.47 arc30 27.3,27.94 v27.16,25.21
  pour Bottom (isolate 0.813, hatched): 10.16,24.77 6.35,24.77 6.35,32.38 7.62,33.66 10.16,33.66
  pour Top (isolate 0.813, hatched): 6.35,20.95 6.35,32.38 7.62,33.66 8.89,33.66 10.16,32.38 14.61,28.57 20.32,27.3 15.24,25.4 15.24,23.5 16.19,15.88
ADJUST  (via drill 0.6)
  Top 0.406: CQ2.E 7.79,62.06 8.64,61.21 CQ1.1 | 22,64.39 CR2.1 | V-TO1.2 30.31,67.31 v32.51,67.31 32.38,67.94 | 20.32,64.77 C-SO8.4 | 20.32,64.77 20.32,65.41 IC2.1 | 39.91,69.92 40.55,69.92 C.A | D4.1 38.41,76.52 39.37,76.2 40.64,72.39 C.A | A.A C..A C.A | 20.32,64.77 20.95,64.77
  Top 1.016: 13.59,61.21 13.97,61.59 13.97,62.8 14.29,63.12 | 22,64.39 20.95,64.39 20.95,64.77
  Top 1.27: v20.32,73.34 22.86,73.09 arc-90 32.38,67.94 | CR1.1 32.77,65.6 v32.51,67.31 | C-MABDT.1 18.68,54.35 17.78,54.61 arc-49 14.29,63.12 arc71 11.43,69.85 10.03,69.85 C-1083.1 | CQ1.1 13.59,61.21
  Bottom 0.406: C-TS.1 8.89,70.36 C-1083.1 10.03,69.22 | A.A 38.42,70.17 v32.51,67.31 | 19.68,68.58 IC2.1
  Bottom 1.27: 19.68,68.58 19.68,71.75 19.24,71.88 | v20.32,73.34 20,72.71 19.24,71.88 | 19.24,71.88 arc-37 12.06,69.85 10.16,69.85 C-1083.1
  pour Bottom (isolate 0.813, hatched): 29.84,69.22 arc-90 31.75,71.12 41.91,71.12 arc-90 43.18,69.85 43.18,67.94 arc-90 41.91,66.67 38.73,66.67 arc-90 38.1,66.04 29.84,66.04
  pour Top (isolate 0.61): 19.68,62.23 26.04,62.23 26.04,64.14 20.95,65.41 20.95,66.04 19.68,66.04
B  (2 unrouted)
B1
  Top 0.406: CQ2.B 7.79,65.58 8.26,66.04 | 8.26,66.04 10.54,66.04 CQ1.3 8.26,66.04
  Bottom 0.406: 6.35,66.67 6.35,88.27
  Bottom 0.61: 6.35,88.27 arc-73 14.61,92.71 35.56,92.71 38.1,90.17 CTRIM3.S R22.S | 6.35,66.67 9.91,66.67 CQ1.3
B2  (2 unrouted)
B-Q1  (2 unrouted)
BATT-  (2 unrouted)
  Bottom 0.406: S1.5 187.32,84.45 191.77,80.01 206.38,80.01 214.63,71.75 229.24,71.75 242.57,58.42 242.57,7.62 241.94,6.99 241.94,6.35 240.66,5.08 MINUS1.1
D  (1 unrouted)
GATE  (2 unrouted)
  Top 0.406: Q4.C 190.35,71.75 R9.1
IN+1
  Top 0.406: 24.43,19.38 V-TO3.1 18.41,20.32 C-MABDT1.3 | TO92S.3 23.5,39.37 23.5,38.1 C-SO1.1
  Top 0.813: 23.5,38.1 23.5,42.55
  pour Bottom (isolate 0.813, hatched): 6.35,37.47 6.35,42.55 13.46,42.67 12.19,37.59
  pour Top (isolate 0.813, rank 3, hatched): 22.86,1.27 22.86,13.34 18.73,15.88 16.83,22.86 27.94,22.86 31.11,24.77 31.11,29.84 23.5,29.84 20,34.86 18.54,38.86 arc90 10.16,37.47 6.35,37.47 6.35,42.55 22.23,42.55 23.5,43.18 23.5,37.47 arc90 27.3,33.66 31.43,33.34 34.29,31.43 34.29,21.59 32.38,19.68 29.84,19.05 arc32 26.04,1.27
  pour Bottom (isolate 0.813, rank 4): 20.32,22.23 27.3,22.23 arc-20 26.04,1.27 22.86,1.27 22.86,14.61 21.59,15.88 17.78,15.88 17.78,20.95
IN-  (1 unrouted)
  Top 0.406: D2.A 11.11,12.38 10.16,11.43 6.99,11.43 6.99,12.21 CQ3.E
  Bottom 0.406: VR10.2 1.27,8.89 1.27,100.33 219.71,100.33 MINUS120.1 218.59,83.97 S1.4 | VR10.2 3.81,8.89 | VIN(-).1 6.35,5.71 VR10.2
  pour Bottom (isolate 0.813, rank 2): 6.35,1.91 1.91,10.79 13.97,10.79 13.97,1.91
  pour Top (isolate 0.813, hatched): 6.35,1.91 6.35,13.97 12.06,13.97 12.06,12.7 13.97,10.79 13.97,1.91
  pour Bottom (isolate 0.813, rank 3, hatched): 5.71,51.44 11.43,51.44 13.34,48.9 13.34,43.18 6.35,43.18
  pour Top (isolate 0.813, rank 4, hatched): 5.71,51.44 11.43,51.44 13.34,48.9 13.34,43.18 6.35,43.18
INPUT+  (via drill 0.6, 1)
  Top 0.406: C-SO8.1 16.83,60.64 v19.05,59.69 V-TO1.1 | C-TS.3 8.89,80.77 C-1083.3 | VC3.1 D1.C | 16.51,66.04 IC2.3 | C-SO8.1 16.51,62.87 | C-SO8.1 16.51,63.5 | C-MABDT.3 v19.05,51.82 VCBRIDGE.1
  Top 0.813: 16.51,63.5 16.51,66.04 16.51,67.94
  Bottom 0.406: 12.06,57.78 IN+.1 | C-1083.3 10.03,81.92 10.79,81.92 14.61,81.28 17.78,80.01 20.32,78.74 24.13,77.47 26.67,75.56 27.3,73.66 25.4,69.22 24.77,62.87 25.4,60.96 25.4,60.33 | v19.05,59.69 22.86,57.78 25.4,60.33 | 16.51,60.33 17.14,59.69 v19.05,59.69 | 25.4,60.33 VC3.1 | v19.05,51.82 v19.05,59.69
  pour Top (isolate 0.813, rank 2, hatched): 22.23,48.26 22.23,55.88 23.5,57.15 27.94,57.15 27.94,60.96 26.67,60.96 26.04,61.59 17.78,61.59 17.78,62.23 17.14,62.87 16.51,62.87 15.88,59.05 9.53,59.05 17.78,48.26
  pour Bottom (isolate 0.813, rank 2, hatched): 11.43,57.15 16.51,48.9 21.59,48.9 21.46,55.24 28.57,60.33 28.57,62.87 26.67,64.77 26.67,67.31 29.84,71.75 43.18,71.75 43.18,77.47 arc16 14.61,82.55 8.89,81.92 8.89,78.11 18.41,78.11 24.13,74.3 23.5,64.14 22.86,62.87 15.88,60.33
MINUS
  Top 0.406: D4.2 36.01,81.47 36.02,88.44 35.56,88.9 33.15,88.9 CTRIM3.A
  Bottom 0.406: R22.E CTRIM3.A
N$1
  Bottom 0.406: VPOT2.A 33.1,41.59 VPOT1.E 32.26,43.05 V_OPTION.2
N$2
  Top 0.406: VR5.2 33.1,35.56 VPOT1.A 36.2,33.66 arc-135 36.2,29.84 VR4.2
  Bottom 0.813: VPOT2.E 31.75,35.13 VPOT1.A
N$3
  Top 0.406: VR8.2 VTRIM1.E
  Bottom 0.813: VTRIM1.E 20.64,24.77
  pour Bottom (isolate 0.813, rank 2, hatched): 17.14,23.5 17.14,25.4 17.46,26.04 18.41,26.04 19.05,26.67 22.23,26.67 22.86,26.04 22.86,23.5
N$4
  Bottom 0.406: VR1.1 20.68,32.07 20.68,30.44
  Bottom 0.813: VTRIM1.A 20.68,30.44
  pour Bottom (isolate 0.813, rank 3, hatched): 17.78,27.94 17.78,28.57 20.32,31.11 22.23,31.11 22.86,30.48 22.86,28.57 22.23,27.94
N$5
  Bottom 0.406: 31.8,83.19 CTRIM3.E R22.A
  Bottom 0.61: VTRIM2.S 28.54,83.86 29.84,83.19 31.8,83.19
N$6
  Bottom 0.406: VTRIM2.A CR3.1
N$7
  Top 0.406: VR3.1 VR7.1
  Bottom 0.406: VR3.1 VC1.1 VC2.2
  pour Bottom (isolate 0.813, rank 3): 15.24,10.79 22.23,10.79 22.23,6.35 15.24,6.35
  pour Top (isolate 0.813, rank 4): 15.24,10.79 22.23,10.79 22.23,2.54 15.24,2.54
N$8  (5 unrouted)
N$9
  Bottom 1.27: C4.- VIN(-)1.1
N$10  (2 unrouted)
N$11  (2 unrouted)
N$12  (1 unrouted)
  Top 0.406: VR3.2 VR7.2 19.64,13.77 D7.C | VR6.1 V_OPTION.1 | VR2.1 VR8.1
  Bottom 0.406: VR3.2 17.21,15.18 15.88,16.51 VR2.1
N$13
  Top 0.406: D6.C 17.78,10.16 D7.A
N$14  (2 unrouted)
N$15  (2 unrouted)
N$16  (via drill 0.6)  (6 unrouted)
  Top 0.406: v48.9,97.79 48.9,6.99 51.44,4.45 52.07,5.08 PLUS5X.1
  Bottom 0.406: S1.2 187.32,95.89 186.06,97.16 49.53,97.16 v48.9,97.79
N$17  (1 unrouted)
N$18
  Top 0.406: T1.3 190.35,69.22 R9.2
N$19  (1 unrouted)
N$20  (3 unrouted)
N$21  (2 unrouted)
N$23  (1 unrouted)
N$24  (1 unrouted)
N$25  (1 unrouted)
N$26  (2 unrouted)
N$27  (2 unrouted)
N$28  (6 unrouted)
N$29  (1 unrouted)
N$30  (2 unrouted)
N$32  (1 unrouted)
N$33  (1 unrouted)
N$34  (4 unrouted)
N$35  (2 unrouted)
N$36  (2 unrouted)
N$37  (2 unrouted)
N$38  (1 unrouted)
N$39  (1 unrouted)
N$40  (2 unrouted)
N$41  (2 unrouted)
N$42  (1 unrouted)
N$43  (4 unrouted)
N$44  (3 unrouted)
N$45  (2 unrouted)
N$46  (2 unrouted)
N$47  (1 unrouted)
N$48  (1 unrouted)
N$49  (1 unrouted)
N$53  (1 unrouted)
N$56  (2 unrouted)
N$58  (2 unrouted)
N$59  (4 unrouted)
N$60  (4 unrouted)
N$61  (2 unrouted)
OUT1  (via drill 0.6)
  Top 0.406: CQ1.2 CQ2.C | v17.14,85.72 16.51,78.16 V-TO1.3 | C-1083.2 13.7,75.56 V-TO1.3 | IC2.2 18.41,67.31 17.78,67.94 C-SO8.7 17.78,70.48 18.1,70.8 | CR2.2 22.54,68.9 | 18.1,70.8 18.41,71.12 V-TO1.3 | C-MABDT.4 30.48,52.07 D1.A VC3.2 29.21,62.23 CR1.2 26.61,66.23 25.92,67.12 CR5.2 | 18.41,70.48 18.1,70.48 18.1,70.8
  Top 0.813: 19.05,70.48 18.41,70.48 18.41,63.5
  Bottom 0.406: 35.94,60.2 36.2,58.42 36.2,56.52 | 35.94,60.2 A..C.A | CQ2.C CQ1.2 13.97,63.5 14.61,64.14 14.61,67.63 15.3,68.32 17.78,68.32 18.41,67.37 IC2.2 | VC3.2 35.94,60.2
  Bottom 1.27: v17.14,85.72 C4.+ CR3.2
  pour Top: 22.86,55.24 29.84,55.24 arc-90 31.75,57.15 arc-64 39.37,56.52 40.64,55.24 43.18,55.24 43.18,48.9 22.86,48.9
  pour Bottom (isolate 0.813, hatched): 7.62,74.93 8.89,74.93 11.43,72.39 11.43,71.75 12.06,71.12 16.51,71.12 13.34,68.58 12.7,67.94 12.7,65.41 10.79,63.5 9.53,63.5 10.16,62.87 12.7,62.23 14.61,62.23 18.99,62.55 23.11,63.82 23.37,75.5 arc33 12.7,79.38 12.06,79.38
  pour Top (isolate 0.813, rank 3, hatched): 38.73,56.52 30.48,56.52 29.21,57.78 29.21,62.23 31.75,62.23 31.75,64.77 28.57,62.87 26.67,64.14 24.13,67.31 18.41,67.31 11.43,74.3 11.43,80.64 14.61,82.55 14.61,90.17 19.68,83.19 19.68,82.55 27.94,78.11 36.2,74.93 38.73,72.39
  pour Bottom (rank 3): 22.86,55.24 29.84,61.59 33.66,65.41 38.1,65.41 38.1,59.69 40.01,55.88 43.81,55.88 43.81,48.9 22.86,48.9
OUT2  (via drill 0.6)
  Top 0.406: 25.4,42.55 25.46,42.55 C-SO1.7 | 25.4,36.2 26.52,36.2 VR5.1 | C-MABDT1.4 v10.16,19.68 | F1.1 D3.A
  Top 0.813: 25.4,42.55 TO92S.2 25.4,36.2
  Bottom 0.406: 9.32,35.19 V-1083.2 V-TS.2 | v10.16,19.68 12.06,24.13 | V-TO3.3 19.68,41.27 22.23,43.81 25.4,43.81 TO92S.2 | F1.1 40.64,8.26
  Bottom 1.27: 34.86,17.78 36.07,15.94 40.64,8.26 | V-1083.2 V-TO3.3 13.34,31.05 12.51,27.69 12.06,24.13
  other vias: 8.26,19.68 8.26,17.78 10.16,17.78
  pour Bottom (isolate 0.813, rank 6, hatched): 10.79,37.47 12.7,38.73 13.97,38.73 13.97,39.37 arc-68 33.66,46.99 arc-90 40.01,40.01 40.01,27.3 38.1,26.67 38.1,19.68 43.18,19.68 43.18,6.35 33.66,6.35 33.66,24.13 34.92,26.67 34.92,44.45 24.45,40.64 21.59,38.42 18.41,34.92 16.51,31.75 13.34,27.3 arc16 13.97,12.38 5.71,12.38 5.71,23.69 10.79,23.81
  pour Top (isolate 0.254, rank 2, hatched): 32.38,19.68 43.18,19.68 43.18,4.45 33.66,4.45 32.38,12.7
OUT+
  Top 0.406: A.C C..C C.C
  pour Bottom (isolate 0.813, rank 2, hatched): 38.73,65.41 43.81,65.41 43.81,55.24 40.64,55.88 38.73,57.78
V+OUT  (4 unrouted)
V-  (21 unrouted)
  Bottom 0.406: VOUT-.1 13.97,45.09 15.88,46.99 46.35,46.99 52.07,52.7 52.07,70.48 53.34,71.75
VIN+  (via drill 0.6)
  Top 0.406: VR9.2 27.79,7.47 VIN(+).1 | v2.54,30.48 1.91,30.48 1.27,29.84 1.27,1.91 2.54,0.64 27.3,0.64 27.94,1.27 Q2.C
  Bottom 0.406: VIN+1.1 VIN(+).1 Q2.C | S1.6 178.28,89.05 170.81,96.52 5.71,96.52 3.81,94.61 3.81,31.75 v2.54,30.48
VIRT-  (via drill 0.6)
  Top 0.406: CQ3.C 9.36,14.44 10.16,15.24 13.34,15.24 14.61,13.97 14.61,13.13 D2.C | D2.C 13.22,11.11 D6.A | v15.88,12.06 15.04,12.06 D2.C
  Bottom 0.406: C2.- 16.71,26.87 15.88,26.04 15.24,26.04 13.97,24.77 13.97,15.24 | 13.97,15.24 15.24,13.97 C3.- | 13.97,15.24 13.97,13.97 v15.88,12.06
  Bottom 0.813: 24.83,35.88 25.02,35.81
  Bottom 1.016: 25.02,35.81 arc72 29.21,41.91 | 24.83,35.88 arc34 19.05,33.4 C2.-
VOUT+  (via drill 0.6)
  Top 0.406: F1.2 VR4.1 39.37,33.02 38.73,45.72 17.78,45.72 12.7,52.7 9.53,53.34 C1.+ | v2.54,59.05 6.99,59.05 VOUT(+)..1
  Top 0.61: C1.+ VCBRIDGE.2
  Bottom 0.406: S1.1 191.34,97.59 189.87,99.06 5.08,99.06 2.54,96.52 v2.54,59.05
  Bottom 1.27: C1.+ 8.26,57.78 VOUT(+)..1
  pour Top (isolate 0.813, hatched): 5.71,55.88 7.62,59.69 10.79,55.24 15.88,50.16 16.51,47.62 18.41,46.99 36.83,46.99 arc-86 43.81,34.92 43.81,20.95 35.56,20.95 38.1,33.66 36.2,36.83 36.2,43.81 30.48,44.45 14.61,44.45 12.06,50.16
VOUT+120  (11 unrouted)
  Top 0.406: D16.C 171.45,74.3 172.09,74.93 172.09,76.2 173.35,77.47 177.65,77.47 R10.1 179.55,75.08 180.97,73.66 | S1.3 180.82,93.83 177.8,90.81 177.8,85.09 180.97,81.92 201.29,81.92 212.72,70.48 217.17,70.48 217.81,69.85 217.71,69.85 Q5.2

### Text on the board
Top: 24112011 | MICHAELS
Bottom: MICHAELS | 24112011
tNames: V_in(+) | V_out(+)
